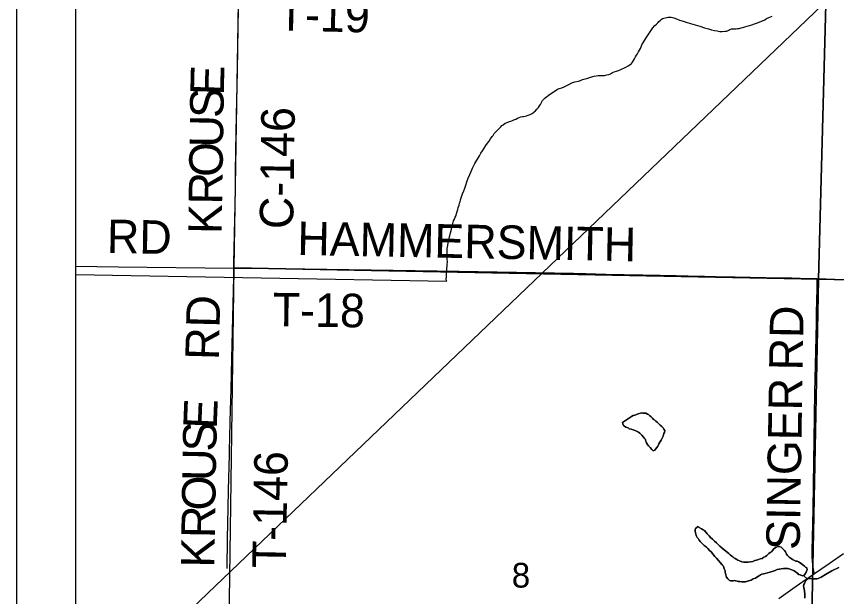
# Model space of a CAD drawing. Extents: x 0 to 34, y 0 to 22.
# Drawn here: x 2 to 3.39, y 14.876 to 15.859 of the extents above; entities that cross this region are included whole.
import ezdxf

# ---------------------------------------------------------------- set-up
doc = ezdxf.new("R2010")
doc.units = 0
for name, color, linetype in [('GM_X_County_Road', 7, 'Continuous'), ('GM_X_County_Road_Text', 7, 'Continuous'), ('GM_X_Major_River', 7, 'Continuous'), ('GM_X_Minor_Lake', 7, 'Continuous'), ('GM_X_Minor_River', 7, 'Continuous'), ('GM_X_Section', 7, 'Continuous'), ('GM_X_Section_Text', 7, 'Continuous'), ('GM_X_State_Route', 7, 'Continuous'), ('GM_X_Township_Road', 7, 'Continuous'), ('GM_X_Township_Road_Text', 7, 'Continuous'), ('SH_Data', 7, 'Continuous')]:
    doc.layers.add(name, color=color, linetype=linetype)

msp = doc.modelspace()

# ---------------------------------------------------------------- linework, layer by layer
at = {"layer": 'GM_X_County_Road'}
for points in [[(2.3685, 15.4328), (2.3686, 15.4414), (2.3706, 15.5396), (2.371, 15.5675), (2.3714, 15.5949), (2.372, 15.6322), (2.3729, 15.6918), (2.3741, 15.7415), (2.3746, 15.7657), (2.3751, 15.8055), (2.3762, 15.8726), (2.377, 15.9329), (2.377, 15.9351)], [(2.1, 15.436), (2.1726, 15.4351), (2.3685, 15.4328)]]:
    msp.add_lwpolyline(points, dxfattribs=at)
at = {"layer": 'GM_X_Major_River'}
for points in [[(3.3934, 14.9254), (3.3818, 14.9197), (3.371, 14.9136), (3.3636, 14.9089), (3.3586, 14.9064), (3.3559, 14.9061), (3.3532, 14.9062), (3.3494, 14.9059), (3.3452, 14.9064), (3.3414, 14.9066), (3.3391, 14.9044), (3.3371, 14.9018), (3.3359, 14.8999), (3.3351, 14.898), (3.3342, 14.8962), (3.3338, 14.8935), (3.3341, 14.8916), (3.3344, 14.8885), (3.335, 14.8855), (3.3354, 14.8836), (3.3357, 14.8816), (3.336, 14.8797), (3.3359, 14.8767), (3.3358, 14.8733)], [(3.3358, 14.8733), (3.3359, 14.8767), (3.336, 14.8797), (3.3357, 14.8816), (3.3354, 14.8836), (3.335, 14.8855), (3.3344, 14.8885), (3.3341, 14.8916), (3.3338, 14.8935), (3.3342, 14.8962), (3.3351, 14.898), (3.3359, 14.8999), (3.3371, 14.9018), (3.3391, 14.9044), (3.3414, 14.9066), (3.3452, 14.9064), (3.3494, 14.9059), (3.3532, 14.9062), (3.3559, 14.9061), (3.3586, 14.9064), (3.3636, 14.9089), (3.371, 14.9136), (3.3818, 14.9197), (3.3934, 14.9254)]]:
    msp.add_lwpolyline(points, dxfattribs=at)
at = {"layer": 'GM_X_Minor_Lake'}
for points in [[(3.0902, 15.1375), (3.0914, 15.1393), (3.0922, 15.1412), (3.0959, 15.1479), (3.0971, 15.1521), (3.098, 15.1543), (3.0985, 15.1573), (3.097, 15.1597), (3.0956, 15.162), (3.0934, 15.1644), (3.0908, 15.1667), (3.0885, 15.1687), (3.0856, 15.1715), (3.0833, 15.1731), (3.0815, 15.1747), (3.0796, 15.1762), (3.0778, 15.1782), (3.0752, 15.1806), (3.0734, 15.1825), (3.0711, 15.1845), (3.0693, 15.1853), (3.0663, 15.1866), (3.064, 15.187), (3.0613, 15.1871), (3.059, 15.1872), (3.0571, 15.1869), (3.0537, 15.1855), (3.0517, 15.1852), (3.0494, 15.1841), (3.0475, 15.1834), (3.0452, 15.1827), (3.0421, 15.1813), (3.0269, 15.1711)], [(3.0269, 15.1711), (3.0421, 15.1813), (3.0452, 15.1827), (3.0475, 15.1834), (3.0494, 15.1841), (3.0517, 15.1852), (3.0537, 15.1855), (3.0571, 15.1869), (3.059, 15.1872), (3.0613, 15.1871), (3.064, 15.187), (3.0663, 15.1866), (3.0693, 15.1853), (3.0711, 15.1845), (3.0734, 15.1825), (3.0752, 15.1806), (3.0778, 15.1782), (3.0796, 15.1762), (3.0815, 15.1747), (3.0833, 15.1731), (3.0856, 15.1715), (3.0885, 15.1687), (3.0908, 15.1667), (3.0934, 15.1644), (3.0956, 15.162), (3.097, 15.1597), (3.0985, 15.1573), (3.098, 15.1543), (3.0971, 15.1521), (3.0959, 15.1479), (3.0922, 15.1412), (3.0914, 15.1393), (3.0902, 15.1375), (3.0882, 15.1349), (3.0878, 15.133), (3.0866, 15.1311), (3.085, 15.1289), (3.083, 15.1259), (3.0814, 15.1241), (3.0791, 15.123), (3.0765, 15.1254), (3.0736, 15.1289), (3.071, 15.1313), (3.0695, 15.134), (3.0677, 15.1367), (3.0666, 15.139), (3.0656, 15.1421), (3.0641, 15.144), (3.0627, 15.146), (3.0597, 15.1495), (3.0579, 15.1515), (3.056, 15.153), (3.0538, 15.1546), (3.0516, 15.1559), (3.0497, 15.1567), (3.0467, 15.1583), (3.0448, 15.1588), (3.0418, 15.1596), (3.0384, 15.1605), (3.0365, 15.1617), (3.0328, 15.1633), (3.0305, 15.1649), (3.0287, 15.1661), (3.0272, 15.1685), (3.0269, 15.1711)], [(3.0269, 15.1711), (3.0272, 15.1685), (3.0287, 15.1661), (3.0305, 15.1649), (3.0328, 15.1633), (3.0365, 15.1617), (3.0384, 15.1605), (3.0418, 15.1596), (3.0448, 15.1588), (3.0467, 15.1583), (3.0497, 15.1567), (3.0516, 15.1559), (3.0538, 15.1546), (3.056, 15.153), (3.0579, 15.1515), (3.0597, 15.1495), (3.0627, 15.146), (3.0641, 15.144), (3.0656, 15.1421), (3.0666, 15.139), (3.0677, 15.1367), (3.0695, 15.134), (3.071, 15.1313), (3.0736, 15.1289), (3.0765, 15.1254), (3.0791, 15.123), (3.0814, 15.1241), (3.083, 15.1259), (3.085, 15.1289), (3.0866, 15.1311), (3.0878, 15.133), (3.0882, 15.1349), (3.0902, 15.1375)], [(3.155, 14.9949), (3.1507, 14.9913), (3.1502, 14.989), (3.1501, 14.9867), (3.1508, 14.984), (3.1511, 14.9817), (3.1525, 14.9783), (3.1532, 14.9763), (3.1554, 14.9736), (3.1569, 14.9713), (3.1587, 14.9693), (3.1606, 14.9673), (3.1624, 14.9654), (3.1654, 14.9626), (3.1672, 14.9614), (3.1691, 14.9598), (3.1713, 14.9575), (3.1742, 14.9543), (3.1772, 14.9516), (3.1794, 14.9492), (3.1812, 14.9469), (3.1834, 14.9441), (3.1864, 14.941), (3.1959, 14.93), (3.1978, 14.9273), (3.1988, 14.9246), (3.1999, 14.9219), (3.2006, 14.9196), (3.2009, 14.9173), (3.2015, 14.915), (3.2019, 14.9127), (3.2026, 14.9108), (3.2033, 14.9089), (3.2051, 14.9058), (3.2077, 14.9038), (3.2099, 14.9029), (3.2122, 14.9025), (3.2145, 14.9028), (3.2164, 14.9031), (3.2187, 14.9026), (3.2209, 14.9022), (3.2228, 14.9017), (3.2255, 14.9013), (3.2289, 14.9008), (3.2319, 14.9007), (3.235, 14.901), (3.2385, 14.902)], [(3.2385, 14.902), (3.235, 14.901), (3.2319, 14.9007), (3.2289, 14.9008), (3.2255, 14.9013), (3.2228, 14.9017), (3.2209, 14.9022), (3.2187, 14.9026), (3.2164, 14.9031), (3.2145, 14.9028), (3.2122, 14.9025), (3.2099, 14.9029), (3.2077, 14.9038), (3.2051, 14.9058), (3.2033, 14.9089), (3.2026, 14.9108), (3.2019, 14.9127), (3.2015, 14.915), (3.2009, 14.9173), (3.2006, 14.9196), (3.1999, 14.9219), (3.1988, 14.9246), (3.1978, 14.9273), (3.1959, 14.93), (3.1864, 14.941), (3.1834, 14.9441), (3.1812, 14.9469), (3.1794, 14.9492), (3.1772, 14.9516), (3.1742, 14.9543), (3.1713, 14.9575), (3.1691, 14.9598), (3.1672, 14.9614), (3.1654, 14.9626), (3.1624, 14.9654), (3.1606, 14.9673), (3.1587, 14.9693), (3.1569, 14.9713), (3.1554, 14.9736), (3.1532, 14.9763), (3.1525, 14.9783), (3.1511, 14.9817), (3.1508, 14.984), (3.1501, 14.9867), (3.1502, 14.989), (3.1507, 14.9913), (3.155, 14.9949)], [(3.2385, 14.902), (3.2446, 14.9037), (3.2485, 14.9058), (3.252, 14.9072), (3.2547, 14.9091), (3.2574, 14.9105), (3.2609, 14.9127), (3.2632, 14.9137), (3.2655, 14.9144), (3.2686, 14.9151), (3.2724, 14.9161), (3.2766, 14.9171), (3.2824, 14.9192), (3.2855, 14.9202), (3.289, 14.9216), (3.2924, 14.9223), (3.2959, 14.9229), (3.2997, 14.9235), (3.3028, 14.9238), (3.305, 14.9238), (3.3069, 14.9233), (3.3088, 14.9229), (3.3107, 14.9224), (3.3175, 14.9195), (3.3201, 14.9179), (3.3219, 14.9167), (3.3242, 14.9151), (3.3253, 14.9132), (3.3279, 14.9127), (3.3321, 14.9111), (3.3344, 14.9125), (3.3368, 14.9151), (3.3388, 14.9188), (3.3396, 14.9215), (3.339, 14.9245), (3.3371, 14.9257), (3.3352, 14.9273), (3.3326, 14.9297), (3.33, 14.9313), (3.3278, 14.9329), (3.3248, 14.9349), (3.3226, 14.9357), (3.3203, 14.9362), (3.3147, 14.9387), (3.3124, 14.9402), (3.3091, 14.9426), (3.3065, 14.9454), (3.305, 14.9477), (3.304, 14.9497), (3.3029, 14.952), (3.3014, 14.9539), (3.2985, 14.9571), (3.2955, 14.9598), (3.2929, 14.9607), (3.2898, 14.9608), (3.2875, 14.9597), (3.2856, 14.9583), (3.2832, 14.9568), (3.2809, 14.9538), (3.2793, 14.952), (3.2773, 14.9505), (3.275, 14.9487), (3.2715, 14.9458), (3.2691, 14.944), (3.2664, 14.9425), (3.2633, 14.9407), (3.2602, 14.9397), (3.2571, 14.9387), (3.2541, 14.9376), (3.251, 14.937), (3.2479, 14.9355), (3.2437, 14.9349), (3.2395, 14.9343), (3.2353, 14.9341), (3.2323, 14.9345), (3.2288, 14.935), (3.2251, 14.9363), (3.2225, 14.9379), (3.2206, 14.9387), (3.218, 14.9403), (3.2157, 14.9415), (3.2139, 14.9431), (3.212, 14.9443), (3.2094, 14.9467), (3.2072, 14.9487), (3.1994, 14.9554), (3.1957, 14.9578), (3.192, 14.9614), (3.189, 14.9641), (3.1861, 14.9673), (3.1827, 14.97), (3.1794, 14.9732), (3.1761, 14.976), (3.1735, 14.9791), (3.1706, 14.9822), (3.168, 14.9854), (3.1658, 14.9877), (3.1636, 14.9893), (3.1606, 14.9909), (3.1568, 14.993), (3.155, 14.9949)], [(3.155, 14.9949), (3.1568, 14.993), (3.1606, 14.9909), (3.1636, 14.9893), (3.1658, 14.9877), (3.168, 14.9854), (3.1706, 14.9822), (3.1735, 14.9791), (3.1761, 14.976), (3.1794, 14.9732), (3.1827, 14.97), (3.1861, 14.9673), (3.189, 14.9641), (3.192, 14.9614), (3.1957, 14.9578), (3.1994, 14.9554), (3.2072, 14.9487), (3.2094, 14.9467), (3.212, 14.9443), (3.2139, 14.9431), (3.2157, 14.9415), (3.218, 14.9403), (3.2206, 14.9387), (3.2225, 14.9379), (3.2251, 14.9363), (3.2288, 14.935), (3.2323, 14.9345), (3.2353, 14.9341), (3.2395, 14.9343), (3.2437, 14.9349), (3.2479, 14.9355), (3.251, 14.937), (3.2541, 14.9376), (3.2571, 14.9387), (3.2602, 14.9397), (3.2633, 14.9407), (3.2664, 14.9425), (3.2691, 14.944), (3.2715, 14.9458), (3.275, 14.9487), (3.2773, 14.9505), (3.2793, 14.952), (3.2809, 14.9538), (3.2832, 14.9568), (3.2856, 14.9583), (3.2875, 14.9597), (3.2898, 14.9608), (3.2929, 14.9607), (3.2955, 14.9598), (3.2985, 14.9571), (3.3014, 14.9539), (3.3029, 14.952), (3.304, 14.9497), (3.305, 14.9477), (3.3065, 14.9454), (3.3091, 14.9426), (3.3124, 14.9402), (3.3147, 14.9387), (3.3203, 14.9362), (3.3226, 14.9357), (3.3248, 14.9349), (3.3278, 14.9329), (3.33, 14.9313), (3.3326, 14.9297), (3.3352, 14.9273), (3.3371, 14.9257), (3.339, 14.9245), (3.3396, 14.9215), (3.3388, 14.9188), (3.3368, 14.9151), (3.3344, 14.9125), (3.3321, 14.9111), (3.3279, 14.9127), (3.3253, 14.9132), (3.3242, 14.9151), (3.3219, 14.9167), (3.3201, 14.9179), (3.3175, 14.9195), (3.3107, 14.9224), (3.3088, 14.9229), (3.3069, 14.9233), (3.305, 14.9238), (3.3028, 14.9238), (3.2997, 14.9235), (3.2959, 14.9229), (3.2924, 14.9223), (3.289, 14.9216), (3.2855, 14.9202), (3.2824, 14.9192), (3.2766, 14.9171), (3.2724, 14.9161), (3.2686, 14.9151), (3.2655, 14.9144), (3.2632, 14.9137), (3.2609, 14.9127), (3.2574, 14.9105), (3.2547, 14.9091), (3.252, 14.9072), (3.2485, 14.9058), (3.2446, 14.9037), (3.2385, 14.902)]]:
    msp.add_lwpolyline(points, dxfattribs=at)
at = {"layer": 'GM_X_Minor_River'}
for p, q in [((2.1, 14.667), (3.7075, 16.2064)), ((2.1, 15.4219), (2.7291, 15.4108)), ((3.3335, 14.9119), (3.3403, 14.9055))]:
    msp.add_line(p, q, dxfattribs=at)
for points in [[(2.9359, 15.7441), (2.9409, 15.7466), (2.9463, 15.7483), (2.9521, 15.7496), (2.9559, 15.751), (2.959, 15.7525), (2.9613, 15.7531), (2.964, 15.7538), (2.9679, 15.7548), (2.9725, 15.7562), (2.9786, 15.7583), (2.9859, 15.7592), (2.9916, 15.759), (2.9962, 15.7592), (3.0004, 15.7602), (3.0039, 15.7612), (3.0066, 15.7623), (3.0101, 15.7641), (3.0128, 15.7655), (3.0166, 15.7665), (3.0201, 15.7675), (3.0232, 15.769), (3.0263, 15.7704), (3.0293, 15.7718), (3.0328, 15.7736), (3.0363, 15.7758), (3.0394, 15.7772), (3.0422, 15.7798), (3.0438, 15.782), (3.0454, 15.7846), (3.0474, 15.7876), (3.049, 15.7909), (3.0506, 15.7935), (3.0522, 15.7962), (3.0542, 15.7995), (3.0558, 15.8021), (3.0571, 15.8051), (3.0587, 15.8081), (3.0599, 15.8111), (3.0624, 15.816), (3.0656, 15.8216), (3.0784, 15.8398), (3.0819, 15.8439), (3.0847, 15.8464), (3.0874, 15.849), (3.0886, 15.8509), (3.0906, 15.8527), (3.0925, 15.8542), (3.0949, 15.8556), (3.0968, 15.8567), (3.0991, 15.857), (3.1018, 15.8573), (3.1045, 15.858), (3.1067, 15.8583), (3.1094, 15.8582), (3.1136, 15.8569), (3.1185, 15.8552), (3.1233, 15.8532), (3.1294, 15.8514), (3.135, 15.8497), (3.1422, 15.8476), (3.1501, 15.845), (3.1581, 15.8429), (3.1656, 15.8403), (3.1724, 15.8386), (3.1777, 15.8369), (3.183, 15.8356), (3.1875, 15.8347), (3.1917, 15.8338), (3.1955, 15.834), (3.2004, 15.8342), (3.2031, 15.8345), (3.205, 15.8352), (3.207, 15.8363), (3.2089, 15.8374), (3.2116, 15.8381), (3.2143, 15.8383), (3.2166, 15.8383), (3.2192, 15.8386), (3.2219, 15.8389), (3.2246, 15.8391), (3.228, 15.8398), (3.2307, 15.8408), (3.2342, 15.8419), (3.238, 15.8429), (3.2419, 15.8439), (3.2461, 15.8449), (3.2507, 15.8466), (3.2557, 15.8484), (3.2681, 15.8537), (3.2708, 15.8559), (3.2747, 15.8573), (3.2774, 15.8587), (3.2805, 15.8597)], [(2.7291, 15.4108), (2.7281, 15.4128), (2.7286, 15.4188), (2.7288, 15.4234), (2.7293, 15.4272), (2.7294, 15.4299), (2.7294, 15.4325), (2.7299, 15.4355), (2.73, 15.439), (2.7302, 15.4431), (2.7299, 15.4477), (2.7298, 15.4542), (2.7296, 15.4599), (2.7297, 15.466), (2.7307, 15.4713), (2.7316, 15.4762), (2.7329, 15.4819), (2.7346, 15.4875), (2.7356, 15.4928), (2.7369, 15.4985), (2.7382, 15.5038), (2.7395, 15.5083), (2.7408, 15.5128), (2.7424, 15.5158), (2.7436, 15.5192), (2.7449, 15.5222), (2.7457, 15.5252), (2.7466, 15.5286), (2.7479, 15.532), (2.7487, 15.5357), (2.75, 15.5395), (2.7509, 15.5429), (2.7517, 15.5452), (2.7526, 15.5482), (2.7543, 15.5538), (2.7559, 15.5587), (2.758, 15.564), (2.7597, 15.5685), (2.7614, 15.5734), (2.7634, 15.579), (2.7656, 15.5854), (2.768, 15.5914), (2.7697, 15.5955), (2.7717, 15.5993), (2.7729, 15.6019), (2.7746, 15.6056), (2.7766, 15.6098), (2.7846, 15.6228), (2.7871, 15.6273), (2.7899, 15.6314), (2.7923, 15.6359), (2.7955, 15.6403), (2.7983, 15.6444), (2.8011, 15.6481), (2.8031, 15.6519), (2.8059, 15.6556), (2.8075, 15.6578), (2.8095, 15.6608), (2.8115, 15.6634), (2.8138, 15.6656), (2.8158, 15.6674), (2.8189, 15.6704), (2.8205, 15.6722), (2.8225, 15.6744), (2.8248, 15.6755), (2.8283, 15.6784), (2.8314, 15.6798), (2.8353, 15.6812), (2.8395, 15.6826), (2.843, 15.684), (2.8461, 15.6854), (2.8488, 15.6869), (2.8519, 15.6883), (2.8546, 15.6893), (2.8572, 15.6896), (2.8592, 15.69), (2.8622, 15.6902), (2.8645, 15.6909), (2.8672, 15.692), (2.8703, 15.6934), (2.8738, 15.6948), (2.8769, 15.697), (2.8793, 15.6992), (2.8816, 15.7021), (2.8844, 15.7051), (2.8864, 15.7077), (2.888, 15.7103), (2.8892, 15.7125), (2.8916, 15.7166), (2.8936, 15.7189), (2.8956, 15.7211), (2.8979, 15.7229), (2.9007, 15.7255), (2.9049, 15.7284), (2.9143, 15.7342), (2.917, 15.736), (2.9197, 15.737), (2.9243, 15.7384), (2.9282, 15.7402), (2.9316, 15.7416), (2.9359, 15.7441)]]:
    msp.add_lwpolyline(points, dxfattribs=at)
at = {"layer": 'GM_X_Section'}
for points in [[(2.3859, 16.4729), (3.3743, 16.4525), (3.3864, 16.4522), (3.3587, 15.4138), (2.3688, 15.4332)], [(3.3864, 16.4522), (4.3846, 16.4315), (4.3576, 15.3927), (3.3587, 15.4138)], [(2.3688, 15.4332), (3.3587, 15.4138), (3.339, 14.4126), (2.3551, 14.4277)], [(4.3576, 15.3927), (4.3359, 14.3884), (3.339, 14.4126), (3.3587, 15.4138)]]:
    msp.add_lwpolyline(points, close=True, dxfattribs=at)
at = {"layer": 'GM_X_State_Route'}
msp.add_lwpolyline([(3.292, 14.8724), (3.3156, 14.8897), (3.3325, 14.9014), (3.3519, 14.9148), (3.377, 14.932), (3.4015, 14.9491)], dxfattribs=at)
at = {"layer": 'GM_X_Township_Road'}
for points in [[(2.1, 18.4074), (2.1, 14.1), (7.3507, 14.1), (7.3542, 14.3107), (7.3767, 15.3155), (7.3854, 16.3696)], [(2.3619, 15.1634), (2.3621, 15.1734), (2.3636, 15.2268), (2.3649, 15.2797), (2.3671, 15.3723), (2.3681, 15.4171), (2.3685, 15.4328)], [(2.3685, 15.4328), (2.4139, 15.4326), (2.7502, 15.4278), (2.8792, 15.4253)], [(2.8792, 15.4253), (2.9441, 15.424), (2.9646, 15.4236), (2.9988, 15.4227), (3.0616, 15.4215), (3.0908, 15.4209), (3.1176, 15.4204), (3.1381, 15.4198), (3.166, 15.4191), (3.1847, 15.4187), (3.2176, 15.4179), (3.2698, 15.4168), (3.314, 15.416), (3.3426, 15.4153), (3.3569, 15.4149)], [(3.3519, 14.9148), (3.3502, 14.922), (3.3491, 14.9294), (3.3486, 14.9359), (3.3483, 14.9429), (3.3483, 14.9534), (3.3495, 14.9994), (3.3498, 15.0243), (3.3508, 15.1052), (3.3517, 15.1412), (3.3529, 15.2221), (3.3554, 15.3396), (3.3558, 15.3577), (3.3566, 15.3975), (3.3568, 15.408), (3.3569, 15.4149)], [(3.3569, 15.4149), (3.4016, 15.4137)], [(2.357, 14.9235), (2.3578, 14.9739), (2.3589, 15.0261), (2.3596, 15.0565), (2.361, 15.1162), (2.3618, 15.1535), (2.3619, 15.1634)]]:
    msp.add_lwpolyline(points, dxfattribs=at)
at = {"layer": 'SH_Data'}
for p, q in [((2, 21), (2, 14)), ((2.1, 20.9), (2.1, 14.1))]:
    msp.add_line(p, q, dxfattribs=at)

# ---------------------------------------------------------------- texts
at = {"layer": 'GM_X_County_Road_Text'}
for s, height, rotation, p in [('E', 0.0568, 88.622, (2.3513, 15.7252)), ('S', 0.0568, 89.1233, (2.3507, 15.687)), ('C-146', 0.05682, 89.1818, (2.4689, 15.4985)), ('U', 0.0568, 89.1312, (2.35, 15.637)), ('O', 0.0568, 89.1329, (2.3492, 15.587)), ('R', 0.0568, 89.1315, (2.3485, 15.5403)), ('K', 0.0568, 89.133, (2.3478, 15.4903)), ('RD', 0.05682, 359.0188, (2.153, 15.4584))]:
    msp.add_text(s, height=height, rotation=rotation, dxfattribs=at).set_placement(p)
at = {"layer": 'GM_X_Section_Text'}
msp.add_text('8', height=0.0419, rotation=0, dxfattribs=at).set_placement((2.8393, 14.8912))
at = {"layer": 'GM_X_Township_Road_Text'}
for s, height, rotation, p in [('T-19', 0.05682, 358.585, (2.4419, 15.8358)), ('HAMMERSMITH', 0.056818, 358.9155, (2.4756, 15.4551)), ('RD', 0.05682, 88.5383, (2.3428, 15.2765)), ('T-18', 0.05682, 359.2931, (2.4339, 15.3341)), ('RD', 0.05682, 89.0127, (3.332, 15.259)), ('SINGER', 0.05682, 89.0543, (3.327, 14.9547)), ('E', 0.0568, 87.7537, (2.3393, 15.1594)), ('S', 0.0568, 88.869, (2.3386, 15.1214)), ('U', 0.0568, 89.0419, (2.3377, 15.0715)), ('T-146', 0.05682, 88.8763, (2.4562, 14.9236)), ('O', 0.0568, 89.0419, (2.3369, 15.0215)), ('R', 0.0568, 89.0436, (2.3361, 14.9748)), ('K', 0.0568, 89.0419, (2.3353, 14.9248))]:
    msp.add_text(s, height=height, rotation=rotation, dxfattribs=at).set_placement(p)

doc.saveas('drawing.dxf')
